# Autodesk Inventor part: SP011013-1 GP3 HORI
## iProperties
Created: 2013-01
Part Number: SP011013-1 GP3 HORI
Material: PVC-U
Document SubType Name: Modeling
Designer: Administrator
Density: 1.4 g/cm^3
Mass: 423.687 g
Surface Area: 2692.09 cm^2
Volume: 302.634 cm^3
Author: Administrator
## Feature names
1. Extrusion1
